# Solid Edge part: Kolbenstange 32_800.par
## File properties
Username: ahadarics
Dokumentum tartalom típus: 0
Author: ahadarics
Last saved by: ahadarics
Revision: 92
Sűrűség: 0,000 kg/m^3
Pontosság: 0,990
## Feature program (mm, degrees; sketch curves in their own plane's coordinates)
base feature "unnamed BaseFeature 1"
thread "unnamed Thread 1"
chamfer "Letörés_1"  SetBackValue2 = 20 deg
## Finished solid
Body 1: solid body, 19 faces, 27 edges, 11 vertices.
  Faces by surface: plane 8, cylinder 5, cone 3, torus 3
  Edges by curve: circle 15, line 7, curve on surface 3, ellipse 2
Bounding box of the edges (mm; curved faces can reach further): 32.000 x 32.000 x 915.500, from (-16, -16, -50.25) to (16, 16, 865.25).
Cylindrical faces by radius (mm): R3.95 x1, R5 x1, R5.8 x1, R6 x1, R16 x1
Conical faces (half-angle, radius in mm at the cone's reference point): 20 deg R5 x1, 30 deg R5.9 x1, 60 deg R4.475 x1
Toroidal faces (ring radius, tube radius in mm): R4.35 r0.4 x2, R4.6 r1.2 x1
Planar faces by outward normal: +x 1, +z 3, -x 1, -z 1, oblique 2
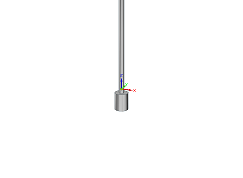
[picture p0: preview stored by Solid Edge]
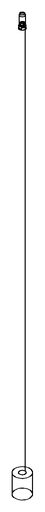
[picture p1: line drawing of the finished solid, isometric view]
